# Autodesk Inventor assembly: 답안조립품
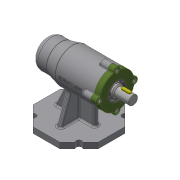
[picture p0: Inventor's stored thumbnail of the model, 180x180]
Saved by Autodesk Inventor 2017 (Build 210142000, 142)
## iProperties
Created: 2019-12
Part Number: 답안조립품
Document SubType Name: Assembly
Designer: 5-08-le
Author: 5-08-le
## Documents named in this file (11)
- C:\Users\5-08-le\Desktop\491204V1032\답안조립품.iam
- C:\Users\5-08-le\Desktop\491204V1032\본체.ipt
- C:\Users\5-08-le\Desktop\491204V1032\축.ipt
- C:\Users\5-08-le\Desktop\491204V1032\키 5 x 5 x 16.ipt
- C:\Users\5-08-le\Desktop\491204V1032\멈춤나사 M3.ipt
- C:\Users\5-08-le\Desktop\491204V1032\베어링 6004.ipt
- C:\Users\5-08-le\Desktop\491204V1032\어댑터슬리브.ipt
- C:\Users\5-08-le\Desktop\491204V1032\볼트 M4.ipt
- C:\Users\5-08-le\Desktop\491204V1032\베어링 51202.ipt
- C:\Users\5-08-le\Desktop\491204V1032\커버.ipt
- C:\Users\5-08-le\Desktop\491204V1032\오일 실.ipt
